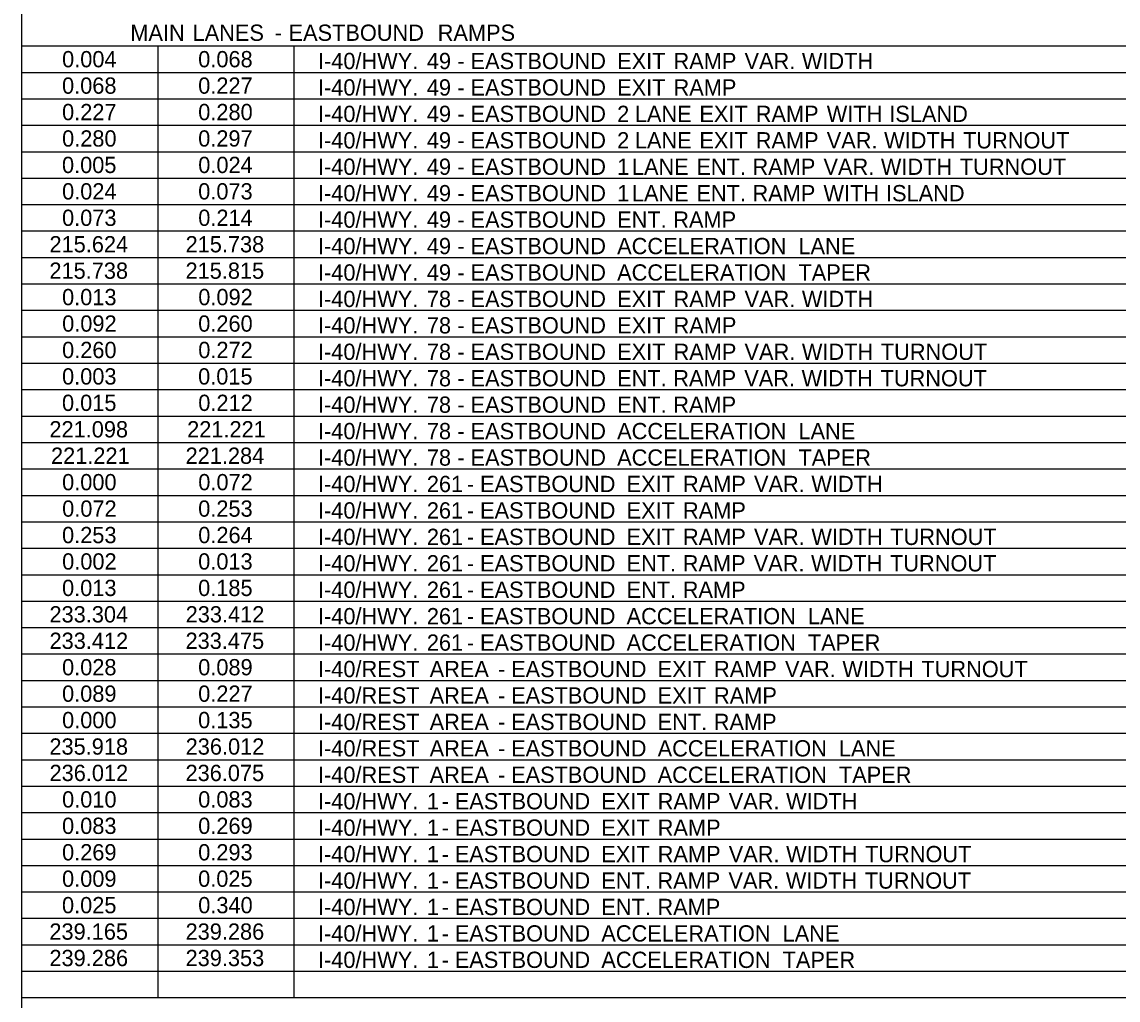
# Model space of a CAD drawing. Extents: x 2261867 to 2275370, y -3124789 to -3122260.
# Drawn here: x 2269400.2 to 2269764, y -3124553.2 to -3124228.5 of the extents above; entities that cross this region are included whole.
import ezdxf

# ---------------------------------------------------------------- set-up
doc = ezdxf.new("R2010")
doc.units = 0
doc.layers.add('Default', color=7, linetype='Continuous')

msp = doc.modelspace()

# ---------------------------------------------------------------- linework, layer by layer
at = {"layer": 'Default'}
for p, q in [((2269400.16, -3124701.59), (2269400.16, -3123657.37)), ((2269400.16, -3124701.59), (2269400.16, -3123657.37)), ((2269400.16, -3124236.52), (2270414.11, -3124236.52)), ((2269445.35, -3124552.42), (2269445.35, -3124236.52)), ((2269490.54, -3124552.42), (2269490.54, -3124236.52)), ((2269490.54, -3124552.42), (2269490.54, -3124236.52)), ((2269400.16, -3124245.29), (2270414.11, -3124245.29)), ((2269445.35, -3124552.42), (2269445.35, -3124245.29)), ((2269400.16, -3124254.07), (2270414.11, -3124254.07)), ((2269400.16, -3124262.84), (2270414.11, -3124262.84)), ((2269400.16, -3124271.62), (2270414.11, -3124271.62)), ((2269400.16, -3124280.39), (2270414.11, -3124280.39)), ((2269400.16, -3124289.17), (2270414.11, -3124289.17)), ((2269400.16, -3124297.94), (2270414.11, -3124297.94)), ((2269400.16, -3124306.72), (2270414.11, -3124306.72)), ((2269400.16, -3124315.49), (2270414.11, -3124315.49)), ((2269400.16, -3124324.27), (2270414.11, -3124324.27)), ((2269400.16, -3124333.04), (2270414.11, -3124333.04)), ((2269400.16, -3124341.82), (2270414.11, -3124341.82)), ((2269400.16, -3124350.59), (2270414.11, -3124350.59)), ((2269400.16, -3124359.37), (2270414.11, -3124359.37)), ((2269400.16, -3124368.14), (2270414.11, -3124368.14)), ((2269400.16, -3124376.92), (2270414.11, -3124376.92)), ((2269400.16, -3124385.69), (2270414.11, -3124385.69)), ((2269400.16, -3124394.47), (2270414.11, -3124394.47)), ((2269400.16, -3124403.24), (2270414.11, -3124403.24)), ((2269400.16, -3124412.02), (2270414.11, -3124412.02)), ((2269400.16, -3124420.79), (2270414.11, -3124420.79)), ((2269400.16, -3124429.57), (2270414.11, -3124429.57)), ((2269400.16, -3124438.34), (2270414.11, -3124438.34)), ((2269400.16, -3124447.12), (2270414.11, -3124447.12)), ((2269400.16, -3124455.89), (2270414.11, -3124455.89)), ((2269400.16, -3124464.67), (2270414.11, -3124464.67)), ((2269400.16, -3124473.44), (2270414.11, -3124473.44)), ((2269400.16, -3124482.22), (2270414.11, -3124482.22)), ((2269400.16, -3124490.99), (2270414.11, -3124490.99)), ((2269400.16, -3124499.77), (2270414.11, -3124499.77)), ((2269400.16, -3124508.54), (2270414.11, -3124508.54)), ((2269400.16, -3124517.32), (2270414.11, -3124517.32)), ((2269400.16, -3124526.09), (2270414.11, -3124526.09)), ((2269400.16, -3124534.87), (2270414.11, -3124534.87)), ((2269400.16, -3124543.64), (2270414.11, -3124543.64)), ((2269400.16, -3124552.42), (2270414.11, -3124552.42)), ((2269400.16, -3124552.42), (2270414.11, -3124552.42))]:
    msp.add_line(p, q, dxfattribs=at)

# ---------------------------------------------------------------- texts
for s, p in [('MAIN', (2269436.14, -3124234.83)), (' LANES', (2269454.81, -3124234.83)), (' EASTBOUND', (2269486.67, -3124234.83)), (' RAMPS', (2269536.18, -3124234.83)), (' -', (2269482.11, -3124234.83)), ('0.004', (2269413.5, -3124243.61)), ('0.068', (2269458.68, -3124243.61)), ('I-40/HWY.', (2269498.44, -3124244.21)), (' 49', (2269532.57, -3124244.21)), (' EASTBOUND', (2269547.09, -3124244.21)), (' EXIT', (2269595.74, -3124244.21)), (' RAMP', (2269614.46, -3124244.21)), (' VAR.', (2269638.03, -3124244.21)), (' WIDTH', (2269657.07, -3124244.21)), (' -', (2269542.72, -3124244.21)), ('0.068', (2269413.49, -3124252.38)), ('0.227', (2269458.68, -3124252.38)), ('I-40/HWY.', (2269498.44, -3124252.99)), (' 49', (2269532.57, -3124252.99)), (' EASTBOUND', (2269547.09, -3124252.99)), (' EXIT', (2269595.74, -3124252.99)), (' RAMP', (2269614.46, -3124252.99)), (' -', (2269542.72, -3124252.99)), ('0.227', (2269413.49, -3124261.16)), ('0.280', (2269458.69, -3124261.16)), ('I-40/HWY.', (2269498.44, -3124261.76)), (' 49', (2269532.57, -3124261.76)), (' EASTBOUND', (2269547.09, -3124261.76)), (' 2', (2269595.74, -3124261.76)), (' LANE', (2269601.63, -3124261.76)), (' EXIT', (2269623.04, -3124261.76)), (' RAMP', (2269641.75, -3124261.76)), (' WITH', (2269665.32, -3124261.76)), (' ISLAND', (2269686.08, -3124261.76)), (' -', (2269542.72, -3124261.76)), ('0.280', (2269413.5, -3124269.93)), ('0.297', (2269458.68, -3124269.93)), ('I-40/HWY.', (2269498.44, -3124270.54)), (' 49', (2269532.57, -3124270.54)), (' -', (2269542.72, -3124270.54)), (' EASTBOUND', (2269547.09, -3124270.54)), (' 2', (2269595.74, -3124270.54)), (' LANE', (2269601.63, -3124270.54)), (' EXIT', (2269623.04, -3124270.54)), (' RAMP', (2269641.75, -3124270.54)), (' VAR.', (2269665.32, -3124270.54)), (' WIDTH', (2269684.37, -3124270.54)), (' TURNOUT', (2269710.58, -3124270.54)), ('0.005', (2269413.47, -3124278.71)), ('0.024', (2269458.7, -3124278.71)), ('I-40/HWY.', (2269498.44, -3124279.31)), (' 49', (2269532.57, -3124279.31)), (' EASTBOUND', (2269547.09, -3124279.31)), (' 1', (2269595.74, -3124279.31)), (' LANE', (2269600.65, -3124279.31)), (' ENT.', (2269622.05, -3124279.31)), (' RAMP', (2269640.67, -3124279.31)), (' VAR.', (2269664.24, -3124279.31)), (' WIDTH', (2269683.29, -3124279.31)), (' TURNOUT', (2269709.5, -3124279.31)), (' -', (2269542.72, -3124279.31)), ('0.024', (2269413.5, -3124287.48)), ('0.073', (2269458.68, -3124287.48)), ('I-40/HWY.', (2269498.44, -3124288.09)), (' 49', (2269532.57, -3124288.09)), (' EASTBOUND', (2269547.09, -3124288.09)), (' 1', (2269595.74, -3124288.09)), (' LANE', (2269600.65, -3124288.09)), (' ENT.', (2269622.05, -3124288.09)), (' RAMP', (2269640.67, -3124288.09)), (' WITH', (2269664.24, -3124288.09)), (' ISLAND', (2269685, -3124288.09)), (' -', (2269542.72, -3124288.09)), ('0.073', (2269413.49, -3124296.26)), ('0.214', (2269458.7, -3124296.26)), ('I-40/HWY.', (2269498.44, -3124296.86)), (' 49', (2269532.57, -3124296.86)), (' EASTBOUND', (2269547.09, -3124296.86)), (' ENT.', (2269595.74, -3124296.86)), (' RAMP', (2269614.37, -3124296.86)), (' -', (2269542.72, -3124296.86)), ('215.624', (2269409.31, -3124305.03)), ('215.738', (2269454.49, -3124305.03)), ('I-40/HWY.', (2269498.44, -3124305.64)), (' 49', (2269532.57, -3124305.64)), (' EASTBOUND', (2269547.09, -3124305.64)), (' ACCELERATION', (2269595.74, -3124305.64)), (' LANE', (2269655.92, -3124305.64)), (' -', (2269542.72, -3124305.64)), ('215.738', (2269409.29, -3124313.81)), ('215.815', (2269454.47, -3124313.81)), ('I-40/HWY.', (2269498.44, -3124314.41)), (' 49', (2269532.57, -3124314.41)), (' EASTBOUND', (2269547.09, -3124314.41)), (' ACCELERATION', (2269595.74, -3124314.41)), (' TAPER', (2269655.92, -3124314.41)), (' -', (2269542.72, -3124314.41)), ('0.013', (2269413.49, -3124322.58)), ('0.092', (2269458.71, -3124322.58)), ('I-40/HWY.', (2269498.44, -3124323.19)), (' 78', (2269532.57, -3124323.19)), (' EASTBOUND', (2269547.09, -3124323.19)), (' EXIT', (2269595.74, -3124323.19)), (' RAMP', (2269614.46, -3124323.19)), (' VAR.', (2269638.03, -3124323.19)), (' WIDTH', (2269657.07, -3124323.19)), (' -', (2269542.72, -3124323.19)), ('0.092', (2269413.52, -3124331.36)), ('0.260', (2269458.69, -3124331.36)), ('I-40/HWY.', (2269498.44, -3124331.96)), (' 78', (2269532.57, -3124331.96)), (' -', (2269542.72, -3124331.96)), (' EASTBOUND', (2269547.09, -3124331.96)), (' EXIT', (2269595.74, -3124331.96)), (' RAMP', (2269614.46, -3124331.96)), ('0.260', (2269413.5, -3124340.13)), ('0.272', (2269458.71, -3124340.13)), ('I-40/HWY.', (2269498.44, -3124340.74)), (' 78', (2269532.57, -3124340.74)), (' EASTBOUND', (2269547.09, -3124340.74)), (' EXIT', (2269595.74, -3124340.74)), (' RAMP', (2269614.46, -3124340.74)), (' VAR.', (2269638.03, -3124340.74)), (' WIDTH', (2269657.07, -3124340.74)), (' TURNOUT', (2269683.28, -3124340.74)), (' -', (2269542.72, -3124340.74)), ('0.003', (2269413.49, -3124348.91)), ('0.015', (2269458.66, -3124348.91)), ('I-40/HWY.', (2269498.44, -3124349.51)), (' 78', (2269532.57, -3124349.51)), (' EASTBOUND', (2269547.09, -3124349.51)), (' ENT.', (2269595.74, -3124349.51)), (' RAMP', (2269614.37, -3124349.51)), (' VAR.', (2269637.94, -3124349.51)), (' WIDTH', (2269656.98, -3124349.51)), (' TURNOUT', (2269683.19, -3124349.51)), (' -', (2269542.72, -3124349.51)), ('0.015', (2269413.47, -3124357.68)), ('0.212', (2269458.71, -3124357.68)), ('I-40/HWY.', (2269498.44, -3124358.29)), (' 78', (2269532.57, -3124358.29)), (' EASTBOUND', (2269547.09, -3124358.29)), (' ENT.', (2269595.74, -3124358.29)), (' RAMP', (2269614.37, -3124358.29)), (' -', (2269542.72, -3124358.29)), ('221.098', (2269409.29, -3124366.46)), ('221.221', (2269455.01, -3124366.46)), ('I-40/HWY.', (2269498.44, -3124367.06)), (' 78', (2269532.57, -3124367.06)), (' EASTBOUND', (2269547.09, -3124367.06)), (' ACCELERATION', (2269595.74, -3124367.06)), (' LANE', (2269655.92, -3124367.06)), (' -', (2269542.72, -3124367.06)), ('221.221', (2269409.82, -3124375.23)), ('221.284', (2269454.5, -3124375.23)), ('I-40/HWY.', (2269498.44, -3124375.84)), (' 78', (2269532.57, -3124375.84)), (' -', (2269542.72, -3124375.84)), (' EASTBOUND', (2269547.09, -3124375.84)), (' ACCELERATION', (2269595.74, -3124375.84)), (' TAPER', (2269655.92, -3124375.84)), ('0.000', (2269413.5, -3124384.01)), ('0.072', (2269458.71, -3124384.01)), ('I-40/HWY.', (2269498.44, -3124384.61)), (' 261', (2269532.57, -3124384.61)), (' EASTBOUND', (2269550.23, -3124384.61)), (' EXIT', (2269598.88, -3124384.61)), (' RAMP', (2269617.6, -3124384.61)), (' VAR.', (2269641.17, -3124384.61)), (' WIDTH', (2269660.22, -3124384.61)), (' -', (2269545.86, -3124384.61)), ('0.072', (2269413.52, -3124392.78)), ('0.253', (2269458.68, -3124392.78)), ('I-40/HWY.', (2269498.44, -3124393.39)), (' 261', (2269532.57, -3124393.39)), (' EASTBOUND', (2269550.23, -3124393.39)), (' EXIT', (2269598.88, -3124393.39)), (' RAMP', (2269617.6, -3124393.39)), (' -', (2269545.86, -3124393.39)), ('0.253', (2269413.49, -3124401.56)), ('0.264', (2269458.7, -3124401.56)), ('I-40/HWY.', (2269498.44, -3124402.16)), (' 261', (2269532.57, -3124402.16)), (' EASTBOUND', (2269550.23, -3124402.16)), (' EXIT', (2269598.88, -3124402.16)), (' RAMP', (2269617.6, -3124402.16)), (' VAR.', (2269641.17, -3124402.16)), (' WIDTH', (2269660.22, -3124402.16)), (' TURNOUT', (2269686.42, -3124402.16)), (' -', (2269545.86, -3124402.16)), ('0.002', (2269413.52, -3124410.33)), ('0.013', (2269458.68, -3124410.33)), ('I-40/HWY.', (2269498.44, -3124410.94)), (' 261', (2269532.57, -3124410.94)), (' EASTBOUND', (2269550.23, -3124410.94)), (' ENT.', (2269598.88, -3124410.94)), (' RAMP', (2269617.51, -3124410.94)), (' VAR.', (2269641.08, -3124410.94)), (' WIDTH', (2269660.12, -3124410.94)), (' TURNOUT', (2269686.33, -3124410.94)), (' -', (2269545.86, -3124410.94)), ('0.013', (2269413.49, -3124419.11)), ('0.185', (2269458.66, -3124419.11)), ('I-40/HWY.', (2269498.44, -3124419.71)), (' 261', (2269532.57, -3124419.71)), (' -', (2269545.86, -3124419.71)), (' EASTBOUND', (2269550.23, -3124419.71)), (' ENT.', (2269598.88, -3124419.71)), (' RAMP', (2269617.51, -3124419.71)), ('233.304', (2269409.31, -3124427.88)), ('233.412', (2269454.52, -3124427.88)), ('I-40/HWY.', (2269498.44, -3124428.49)), (' 261', (2269532.57, -3124428.49)), (' EASTBOUND', (2269550.23, -3124428.49)), (' ACCELERATION', (2269598.88, -3124428.49)), (' LANE', (2269659.06, -3124428.49)), (' -', (2269545.86, -3124428.49)), ('233.412', (2269409.33, -3124436.66)), ('233.475', (2269454.47, -3124436.66)), ('I-40/HWY.', (2269498.44, -3124437.26)), (' 261', (2269532.57, -3124437.26)), (' EASTBOUND', (2269550.23, -3124437.26)), (' ACCELERATION', (2269598.88, -3124437.26)), (' TAPER', (2269659.06, -3124437.26)), (' -', (2269545.86, -3124437.26)), ('0.028', (2269413.49, -3124445.43)), ('0.089', (2269458.68, -3124445.43)), ('I-40/REST', (2269498.44, -3124446.04)), (' AREA', (2269533.5, -3124446.04)), (' EASTBOUND', (2269560.53, -3124446.04)), (' EXIT', (2269609.19, -3124446.04)), (' RAMP', (2269627.9, -3124446.04)), (' VAR.', (2269651.47, -3124446.04)), (' WIDTH', (2269670.52, -3124446.04)), (' TURNOUT', (2269696.73, -3124446.04)), (' -', (2269556.16, -3124446.04)), ('0.089', (2269413.49, -3124454.21)), ('0.227', (2269458.68, -3124454.21)), ('I-40/REST', (2269498.44, -3124454.81)), (' AREA', (2269533.5, -3124454.81)), (' EASTBOUND', (2269560.53, -3124454.81)), (' EXIT', (2269609.19, -3124454.81)), (' RAMP', (2269627.9, -3124454.81)), (' -', (2269556.16, -3124454.81)), ('0.000', (2269413.5, -3124462.98)), ('0.135', (2269458.66, -3124462.98)), ('I-40/REST', (2269498.44, -3124463.59)), (' AREA', (2269533.5, -3124463.59)), (' EASTBOUND', (2269560.53, -3124463.59)), (' ENT.', (2269609.19, -3124463.59)), (' RAMP', (2269627.81, -3124463.59)), (' -', (2269556.16, -3124463.59)), ('235.918', (2269409.29, -3124471.76)), ('236.012', (2269454.52, -3124471.76)), ('I-40/REST', (2269498.44, -3124472.36)), (' AREA', (2269533.5, -3124472.36)), (' EASTBOUND', (2269560.53, -3124472.36)), (' ACCELERATION', (2269609.19, -3124472.36)), (' LANE', (2269669.36, -3124472.36)), (' -', (2269556.16, -3124472.36)), ('236.012', (2269409.33, -3124480.53)), ('236.075', (2269454.47, -3124480.53)), ('I-40/REST', (2269498.44, -3124481.14)), (' AREA', (2269533.5, -3124481.14)), (' -', (2269556.16, -3124481.14)), (' EASTBOUND', (2269560.53, -3124481.14)), (' ACCELERATION', (2269609.19, -3124481.14)), (' TAPER', (2269669.36, -3124481.14)), ('0.010', (2269413.5, -3124489.31)), ('0.083', (2269458.68, -3124489.31)), ('I-40/HWY.', (2269498.44, -3124489.91)), (' 1', (2269532.57, -3124489.91)), (' EASTBOUND', (2269541.84, -3124489.91)), (' EXIT', (2269590.5, -3124489.91)), (' RAMP', (2269609.21, -3124489.91)), (' VAR.', (2269632.78, -3124489.91)), (' WIDTH', (2269651.83, -3124489.91)), (' -', (2269537.47, -3124489.91)), ('0.083', (2269413.49, -3124498.08)), ('0.269', (2269458.68, -3124498.08)), ('I-40/HWY.', (2269498.44, -3124498.69)), (' 1', (2269532.57, -3124498.69)), (' EASTBOUND', (2269541.84, -3124498.69)), (' EXIT', (2269590.5, -3124498.69)), (' RAMP', (2269609.21, -3124498.69)), (' -', (2269537.47, -3124498.69)), ('0.269', (2269413.49, -3124506.86)), ('0.293', (2269458.68, -3124506.86)), ('I-40/HWY.', (2269498.44, -3124507.46)), (' 1', (2269532.57, -3124507.46)), (' EASTBOUND', (2269541.84, -3124507.46)), (' EXIT', (2269590.5, -3124507.46)), (' RAMP', (2269609.21, -3124507.46)), (' VAR.', (2269632.78, -3124507.46)), (' WIDTH', (2269651.83, -3124507.46)), (' TURNOUT', (2269678.04, -3124507.46)), (' -', (2269537.47, -3124507.46)), ('0.009', (2269413.49, -3124515.63)), ('0.025', (2269458.66, -3124515.63)), ('I-40/HWY.', (2269498.44, -3124516.24)), (' 1', (2269532.57, -3124516.24)), (' EASTBOUND', (2269541.84, -3124516.24)), (' ENT.', (2269590.5, -3124516.24)), (' RAMP', (2269609.12, -3124516.24)), (' VAR.', (2269632.69, -3124516.24)), (' WIDTH', (2269651.74, -3124516.24)), (' TURNOUT', (2269677.95, -3124516.24)), (' -', (2269537.47, -3124516.24)), ('0.025', (2269413.47, -3124524.41)), ('0.340', (2269458.69, -3124524.41)), ('I-40/HWY.', (2269498.44, -3124525.01)), (' 1', (2269532.57, -3124525.01)), (' -', (2269537.47, -3124525.01)), (' EASTBOUND', (2269541.84, -3124525.01)), (' ENT.', (2269590.5, -3124525.01)), (' RAMP', (2269609.12, -3124525.01)), ('239.165', (2269409.28, -3124533.18)), ('239.286', (2269454.49, -3124533.18)), ('I-40/HWY.', (2269498.44, -3124533.79)), (' 1', (2269532.57, -3124533.79)), (' EASTBOUND', (2269541.84, -3124533.79)), (' ACCELERATION', (2269590.5, -3124533.79)), (' LANE', (2269650.67, -3124533.79)), (' -', (2269537.47, -3124533.79)), ('239.286', (2269409.3, -3124541.96)), ('239.353', (2269454.49, -3124541.96)), ('I-40/HWY.', (2269498.44, -3124542.56)), (' 1', (2269532.57, -3124542.56)), (' EASTBOUND', (2269541.84, -3124542.56)), (' ACCELERATION', (2269590.5, -3124542.56)), (' TAPER', (2269650.67, -3124542.56)), (' -', (2269537.47, -3124542.56))]:
    msp.add_text(s, height=5.4, dxfattribs=at).set_placement(p)

doc.saveas('drawing.dxf')
